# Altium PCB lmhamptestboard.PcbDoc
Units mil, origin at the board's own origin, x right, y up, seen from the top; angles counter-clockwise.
Board outline 1050 x 1270 mil, 2 copper layers (L1, L2), stack 62.8 mil thick; 40 components, 20 nets, 96 pads, 9 vias.
Unrouted connection lines stored in the file: 1.
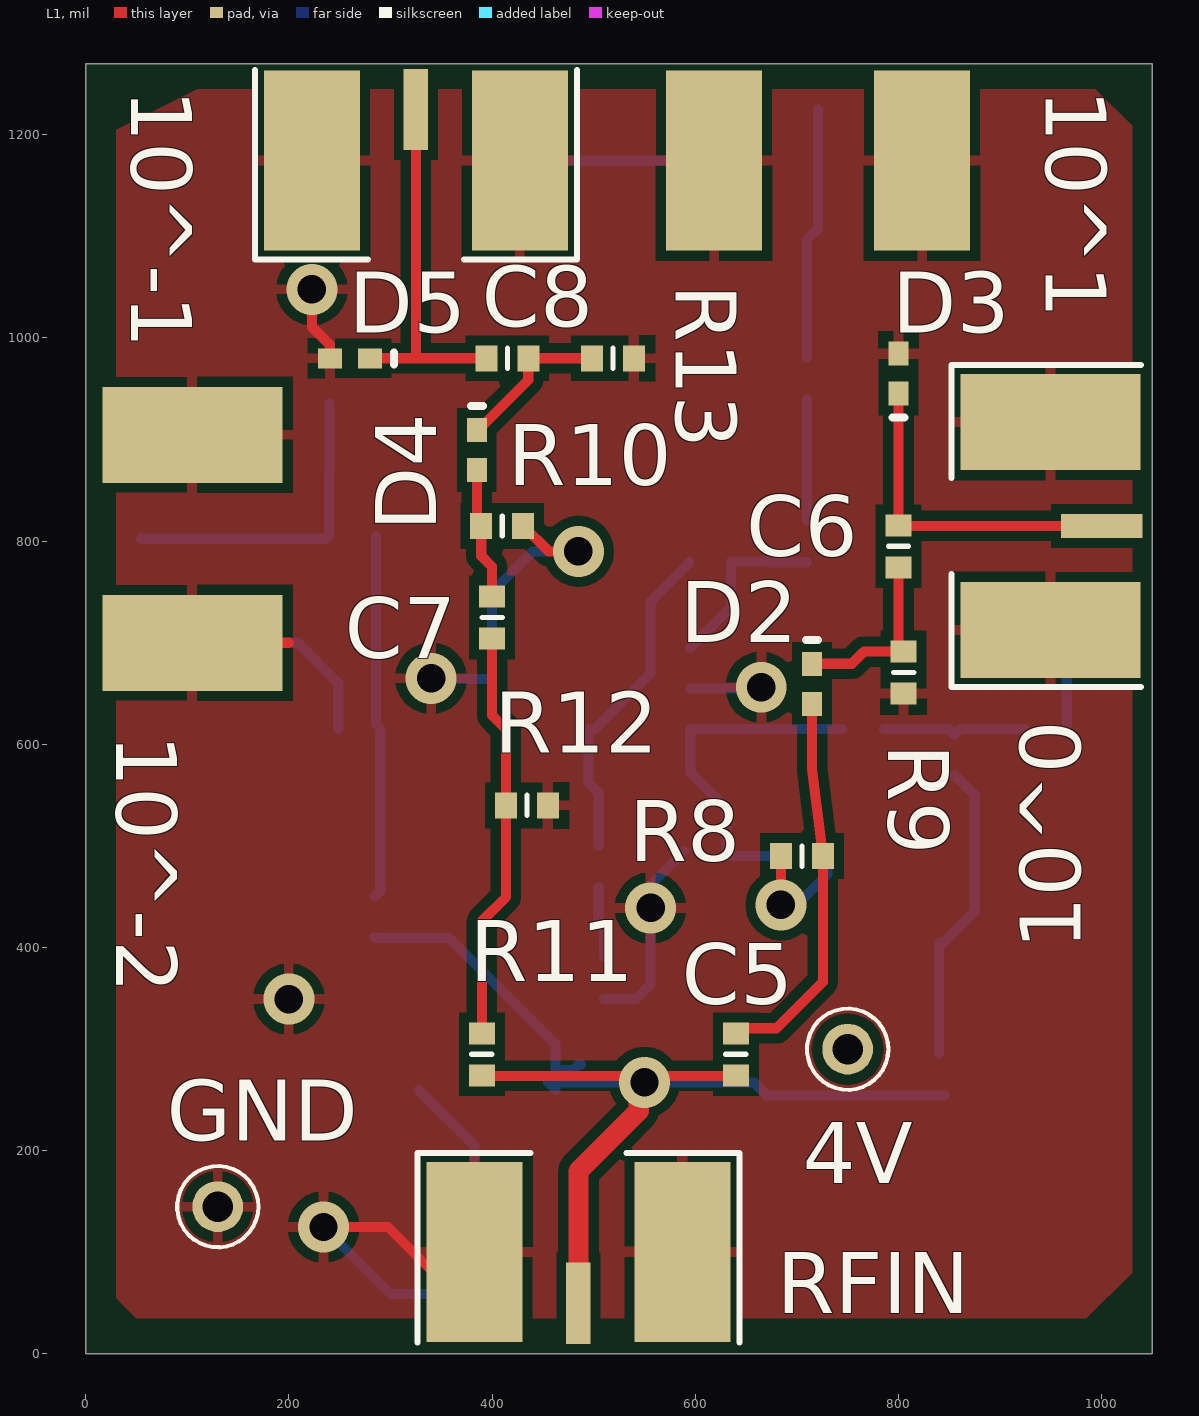
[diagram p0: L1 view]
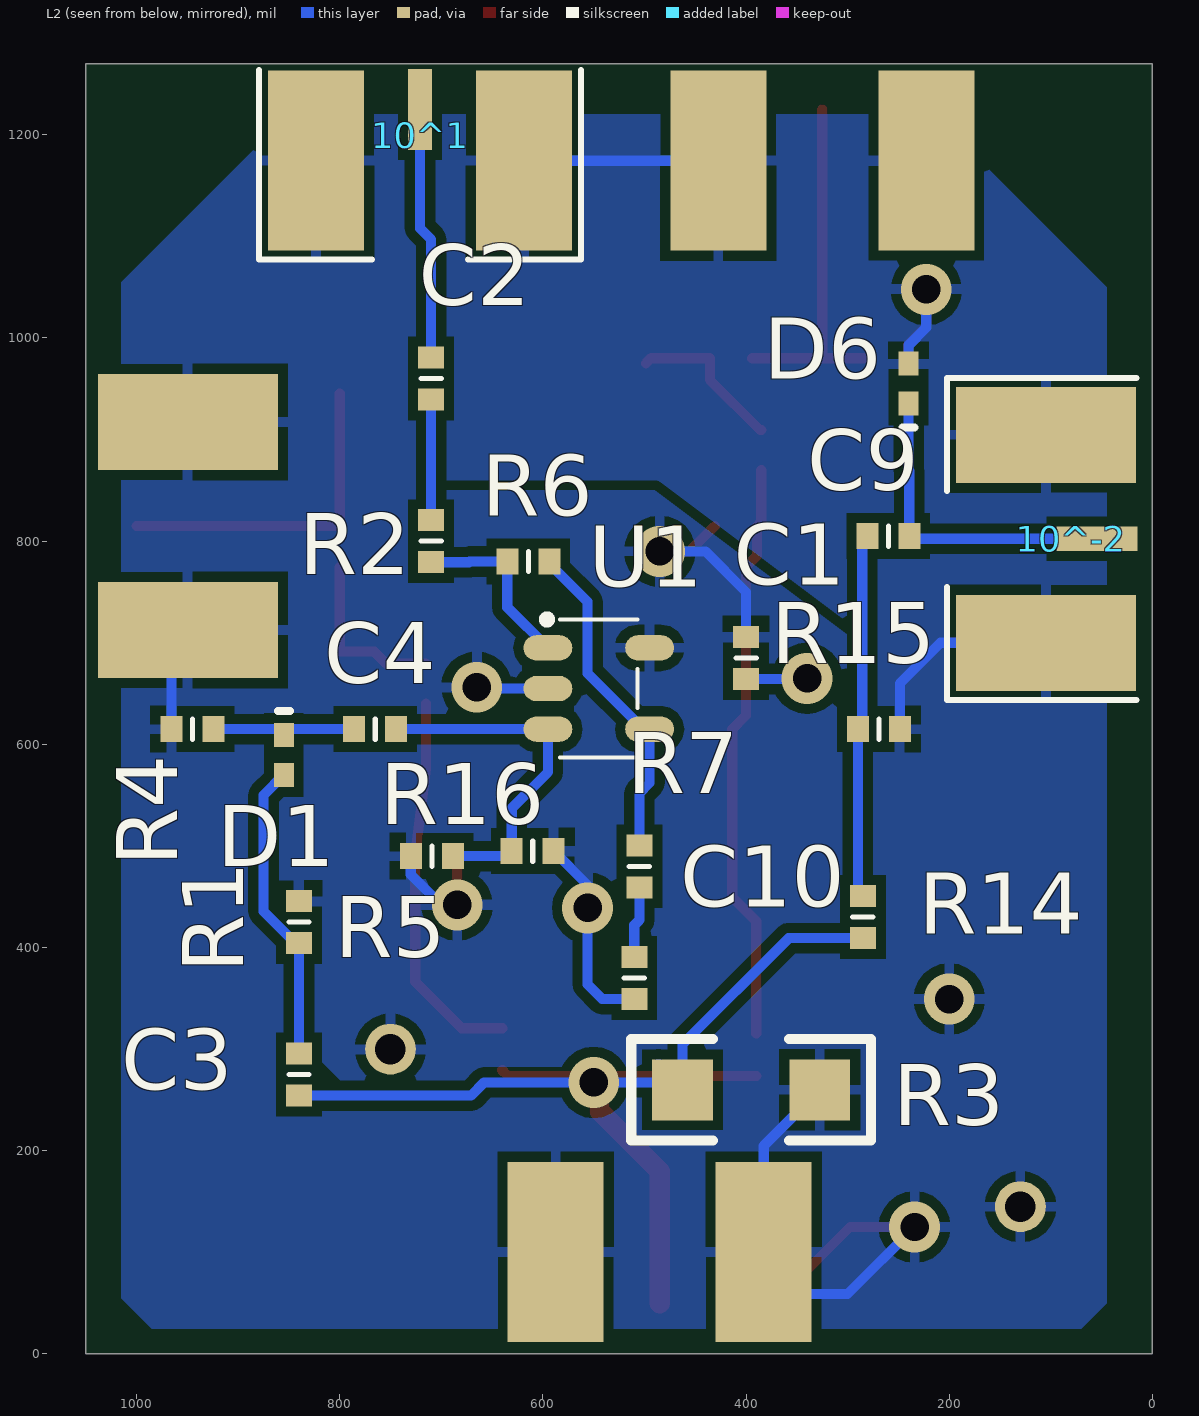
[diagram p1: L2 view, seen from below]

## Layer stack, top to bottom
Top Solder: solder mask 0.1, Solder Resist, Dk 0
L1: signal copper 1.4
Core: dielectric 60, FR-4, Dk 4.6
L2: signal copper 1.4
Bottom Solder: solder mask 0.1, Solder Resist, Dk 0

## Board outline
0,0 1050,0 1050,1270 0,1270

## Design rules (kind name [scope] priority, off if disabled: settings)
BoardOutlineClearance [All] p1: gap=15 ignorepadtopadclearanceinfootprint=FALSE
Clearance [All] p1: gap=10 ignorepadtopadclearanceinfootprint=FALSE except(0: Arc-Text Arc-Hole Track-Text Track-Hole SMDPad-Text SMDPad-Hole THPad-Text THPad-Hole Via-Text Via-Hole Fill-Text Fill-Hole Poly-Text Poly-Hole Region-Text Region-Hole Text-Text Text-Hole)
ComponentClearance [All] p1 off: gap=10 collisioncheckmode=3 verticalgap=10 showdistances=FALSE
Height [All] p1 off: minheight=0 maxheight=1000 prefheight=500
HoleSize [All] p1: absolutevalues=TRUE maxlimit=265 minlimit=13 maxpercent=80.000 minpercent=20.000
HoleToHoleClearance [All] p1: gap=10 allowstackedmicrovias=FALSE
MinimumAnnularRing [All] p1: minimumring=7
MinimumSolderMaskSliver [All] p1: minsoldermaskwidth=0
PolygonConnect [All] p1: connectstyle=Relief reliefconductorwidth=10 reliefentries=4 polygonreliefangle="90 Angle" airgapwidth=10
RoutingVias [All] p1: holewidth=28 width=50 viastyle="Through Hole" minholewidth=28 minwidth=50 maxholewidth=28 maxwidth=50
SilkToSilkClearance [All] p1: silktosilkclearance=0
SilkToSolderMaskClearance [IsPad] p1: minsilkscreentomaskgap=6 clearancetoexposedcopper=TRUE
SolderMaskExpansion [All] p1: expansion=4
Width [All] p1: maxlimit=20 minlimit=10 preferedwidth=10
23 further rules are at their usual default settings.

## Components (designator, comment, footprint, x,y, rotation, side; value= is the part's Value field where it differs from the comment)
4V "TEST-POINT-SURFACE-MOUNT" TPH0.5S 750,300 r0 top
10^0 "UCBBJE20-1" CNSMAPCBEDGE3 1044,815 r180 top
10^1 "UCBBJE20-1" CNSMAPCBEDGE3 720.91,1269 r270 bottom
10^-1 "UCBBJE20-1" CNSMAPCBEDGE3 325,1269 r270 top
10^-2 "UCBBJE20-1" CNSMAPCBEDGE3 10.51,802.36 r0 bottom
C1 "CAPACITOR-0402" CC0402N1X 400,685 r270 bottom value=100nF
C2 "CAPACITOR-0402" CC0402N1X 710,960 r270 bottom value=47n
C3 "CAPACITOR-0402" CC0402N1X 840,275 r90 bottom value=47n
C4 "CAPACITOR-0402" CC0402N1X 765,615 r180 bottom value=47n
C5 "CAPACITOR-0402" CC0402N1X 640,295 r90 top value=47n
C6 "CAPACITOR-0402" CC0402N1X 800,795 r90 top value=47n
C7 "CAPACITOR-0402" CC0402N1X 400,725 r90 top value=47n
C8 "CAPACITOR-0402" CC0402N1X 415,980 r180 top value=47n
C9 "CAPACITOR-0402" CC0402N1X 260,805 r180 bottom value=47n
C10 "CAPACITOR-0402" CC0402N1X 510,370 r90 bottom value=47n
D1 "Diode" 0402-A 855,589.69 r270 bottom
D2 "Diode" 0402-A 715,659.69 r270 top
D3 "Diode" 0402-A 800,965 r90 top
D4 "Diode" 0402-A 385,889.69 r270 top
D5 "Diode" 0402-A 260,980 r180 top
D6 "Diode" 0402-A 240,955 r90 bottom
GND "TEST-POINT-SURFACE-MOUNT" TPH0.5S 130,145 r90 top
R1 "RES0402" CC0402N1X 840,425 r90 bottom value=10k
R2 "RES0402" CC0402N1X 710,800 r270 bottom value=0
R3 "RES1206" 1206 395,260 r0 bottom value=50
R4 "RES0402" CC0402N1X 945,615 r180 bottom value=10k
R5 "RES0402" CC0402N1X 709.33,490 r0 bottom value=10k
R6 "RES0402" CC0402N1X 614.33,780 r180 bottom value=400
R7 "RES0402" CC0402N1X 505,480 r90 bottom value=44.44
R8 "RES0402" CC0402N1X 705,490 r180 top value=10k
R9 "RES0402" CC0402N1X 805,670.67 r90 top value=10k
R10 "RES0402" CC0402N1X 410,815 r0 top value=10k
R11 "RES0402" CC0402N1X 390,295 r270 top value=7.5k
R12 "RES0402" CC0402N1X 434.33,540 r180 top value=1k
R13 "RES0402" CC0402N1X 519.1,980 r180 top value=10k
R14 "RES0402" CC0402N1X 285,430 r270 bottom value=95k
R15 "RES0402" CC0402N1X 269.33,615 r0 bottom value=1k
R16 "RES0402" CC0402N1X 610,495 r0 bottom value=10k
RFIN "UCBBJE20-1" CNSMAPCBEDGE3 485,6 r90 top
U1 "LMH6629" SOT23-5 545,655 r180 bottom

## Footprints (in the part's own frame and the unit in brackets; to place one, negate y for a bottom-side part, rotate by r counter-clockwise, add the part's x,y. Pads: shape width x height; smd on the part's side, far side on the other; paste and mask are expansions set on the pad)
0402-A [mm] "Chip Inductor, Body 1.0x0.5mm, IPC High Density"
  rect 0.6x0.5 smd: 1(0.5,0) 2(-0.5,0)
  silkscreen extent -1.1,-0.15 -1.1,0.15, body extent -0.55,-0.3 0.55,0.3, height 0.55
1206 [mil]
  rect 60x60 smd: 1(-67.5,0) 2(67.5,0)
  silkscreen extent -118,-50 118,50
CC0402N1X [mm] "Chip capacitor 0402"
  rect 0.55x0.65 smd mask+0.025: 1(-0.525,0) 2(0.525,0)
  silkscreen extent 0,-0.25 0,0.25, body extent -0.51,-0.25 0.51,0.25, height 0.5
CNSMAPCBEDGE3 [mm] "SMA PCB edge female EL-FS090-03"
  rect 2.032x0.61 smd: 1(1.118,0)
  rect 4.5x2.4 smd: 2(2.4,2.6) 3(2.4,-2.6)
  rect 4.5x2.4 smd far side: 2(2.4,2.6) 3(2.4,-2.6)
  silkscreen extent 0.13,-4.02 4.88,4.02, body extent -9.6,-3.15 3.8,3.15, height 3.5
SOT23-5 [mil]
  oval 48x25 smd mask+2: 1(-50,40) 2(-50,0) 3(-50,-40) 4(50,-40) 5(50,40)
  silkscreen extent -55,-68 38,72, body extent -50,-61 50,61, height 57
TPH0.5S [mil] "Test point TH 0.5mm slim"
  round 50 hole 30: 1(0,0)
  silkscreen extent -40,-40 40,40

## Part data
10^0 10^1 10^-1 10^-2 RFIN: "75R Circuit Board Bulkhead Edge Mount  Coax “BNC” Style Receptacle", Manufacturer=Trompeter
C1 C2 C3 C4 C5 C6 C7 C8 C9 C10: "capacitor", Manufacturer #1="IPC SM-782 STD.", Size / Package=0402
D1 D2 D3 D4 D5 D6: "Default Diode"
R1 R2 R4 R5 R6 R7 R8 R9 R10 R11 R12 R13 R14 R15 R16: "SURFACE MOUNT RESISTOR 0.020 X 0.040 INCHES, 1/16W", Manufacturer #1="IPC SM-782 STD."
R3: "SURFACE MOUNT RESISTOR 0.062 X 0.126 INCHES, 1/8W", Manufacturer #1="IPC SM-782 STD."
U1: library part LMH6624

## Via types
v1: diameter 50, hole 28, L1 to L2, 9 vias

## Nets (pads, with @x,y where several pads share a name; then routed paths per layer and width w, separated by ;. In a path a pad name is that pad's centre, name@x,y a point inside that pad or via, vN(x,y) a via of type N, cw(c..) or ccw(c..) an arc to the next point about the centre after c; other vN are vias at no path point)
+4V: 4V.1 C1.1 R1.2 R5.2 R8.2 R10.2 U1.5 | length 334.7
  L1 w10: R10.2 455.67,790 v1(485,790) ; v1(684.33,442) R8.2
  L2 w10: C1.1 400,750 440,790 v1(485,790) ; v1(684.33,442) 700,442 730,472 R5.2
GND: 10^0.2 10^0.3 10^1.2 10^1.3 10^-1.2 10^-1.3 10^-2.2 10^-2.3 C1.2 C10.1 D3.1 D5.1 D6.1 GND.1 R3.1 R4.1 R9.1 R12.1 R13.1 R15.1 R16.1 RFIN.2 RFIN.3 U1.2 | length 1995.5
  L1 w10: 10^-2.2@64,700 105,700 200,700 ; v1(222.64,1047.86) 222.64,1010.99 240.31,993.31 D5.1 ; v1(234.1,125) 297.64,125 382.64,40 RFIN.2@382.64,100.49 ; 10^1.2@618.54,1174.51 10^1.2@618.54,1230 ; 10^0.2@880,712.64 10^0.2@949.51,712.64
  L2 w10: 10^-2.2@40,700 105,700 208.66,700 248.66,660 R15.1 ; v1(222.64,1047.86) 222.64,1010.36 240,993 D6.1 ; v1(234.1,125) 300.1,59 382.64,59 382.64,100.49 382.64,204.86 R3.1 ; v1(340,665) 340.67,664.33 C1.2 ; 10^-1.2@427.36,1174.51 618.54,1174.51 10^1.2@618.54,1216 ; C10.1 541.49,349.33 556,363.84 v1(556,439) 556,461.67 R16.1 ; U1.2 663.67,655 v1(665,656.33) ; 10^0.2@949.51,712.64 949.51,699.27 965.67,683.11 R4.1
  other v1: 200,349.33
NetC2_2: C2.2 R2.1 | length 118.7
  L2 w10: R2.1 C2.2
NetC3_2: C3.2 D1.1 R1.1 | length 299.2
  L2 w10: C3.2 R1.1 843.5,404.33 875,435.83 875,550 D1.1
NetC4_1: C4.1 D1.2 R4.2 | length 143.3
  L2 w10: C4.1 849.37,615 D1.2 860.63,615 R4.2
NetC4_2: C4.2 R5.1 R16.2 U1.3 | length 344.2
  L2 w10: R5.1 635.67,490 R16.2 630.67,537 595,572.67 U1.3 C4.2
NetC5_2: C5.2 D2.1 R8.1 | length 378.9
  L1 w10: C5.2@640,320.67 680,320.67 725.67,366.34 R8.1 715,575.67 D2.1
NetC6_1: C6.1 D2.2 R9.2 | length 180
  L1 w10: D2.2 754,679.37 765.97,691.34 R9.2 800,696.34 C6.1
NetC7_1: C7.1 R11.1 R12.2 | length 404.1
  L1 w10: R11.1 390,426 413.66,449.66 R12.2 413.66,615 400,628.66 C7.1
NetC7_2: C7.2 D4.1 R10.1 | length 130.5
  L1 w10: D4.1 385,819.33 R10.1 389.33,785.67 400,775 C7.2
NetC8_1: C8.1 D4.2 R13.2 | length 157.5
  L1 w10: D4.2 386.37,909.37 435.67,958.67 C8.1 493.66,980 R13.2@498.66,975
NetC9_1: C9.1 R14.1 R15.2 | length 351.4
  L2 w10: R14.1 290,455.67 R15.2 ; R15.2@285.67,620 C9.1@285.67,805
NetC10_2: C10.2 R7.1 | length 70.7
  L2 w10: R7.1 505,427 510,422 C10.2
NetR2_2: R2.2 R6.1 U1.1 | length 176.8
  L2 w10: U1.1 635,735 R6.1 672,780 672.67,779.33 R2.2
NetR6_2: R6.2 R7.2 U1.4 | length 327.9
  L2 w10: R7.2 505,552 495,562 U1.4 501,615 556,670 556,740.43 593.66,778.09 R6.2
RF_OUTA: 10^1.1 C2.1 | length 248.8
  L2 w10: C2.1 710,1097 720.91,1107.91 10^1.1
RF_OUTB: 10^0.1 C6.2 D3.2 | length 326
  L1 w10: C6.2 800,815 10^0.1 ; C6.2@800,820 D3.2
RF_OUTC: 10^-1.1 C8.2 D5.2 | length 359.6
  L1 w10: D5.2 325,980 ; 10^-1.1 325,980 ; C8.2 325,980
RF_OUTD: 10^-2.1 C9.2 D6.2 | length 316.5
  L2 w10: 10^-2.1 236.69,802.36 C9.2 239.33,869 240,869.67 D6.2
RFIN: C3.1 C5.1 R3.2 R11.2 R14.2 RFIN.1 | length 1206.7
  L1 w10: R11.2@390,273.66 544.33,273.66 550,273.66 634.33,273.66 C5.1@640,279.33
  L1 w20: RFIN.1 485,180 544.33,239.33 v1@544.33,273.66 ; v1(550,267.35) v1@550,273.66
  L2 w10: R14.2@284.16,410.16 R14.2 358.03,409.33 462.5,304.86 R3.2@462.5,279.33 ; R3.2@487.5,285 485,285 479.33,279.33 R3.2@462.5,279.33 ; C3.1@845,254.33 C3.1 670.67,254.33 657.65,267.35 v1(550,267.35) R3.2@462.5,267.35 ; R3.2@462.5,267.35 455.15,267.35 R3.2 R3.2@462.5,267.35 ; R3.2@462.5,267.35 R3.2@462.5,279.33

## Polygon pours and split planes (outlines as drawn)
GND on L2 "L3_+7V" (solid, remove dead copper, pour order 6): 45,1050 215,1220 850,1220 1015,1055 1015,55 985,25 70,25 45,50
+4V on L2 "L3_+7V" (solid, remove dead copper, pour order 4): 852.5,850 885,817.5 885,355 775,245 375,245 290,330 290,700 490,850
GND on L1 "L3_+7V" (solid, remove dead copper, pour order 0): 110,1245 993.67,1245 1030,1208.67 1030,80 985,35 50,35 30,55 30,1205

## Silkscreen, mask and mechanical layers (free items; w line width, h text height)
Mechanical 1:
  the board outline again, w10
